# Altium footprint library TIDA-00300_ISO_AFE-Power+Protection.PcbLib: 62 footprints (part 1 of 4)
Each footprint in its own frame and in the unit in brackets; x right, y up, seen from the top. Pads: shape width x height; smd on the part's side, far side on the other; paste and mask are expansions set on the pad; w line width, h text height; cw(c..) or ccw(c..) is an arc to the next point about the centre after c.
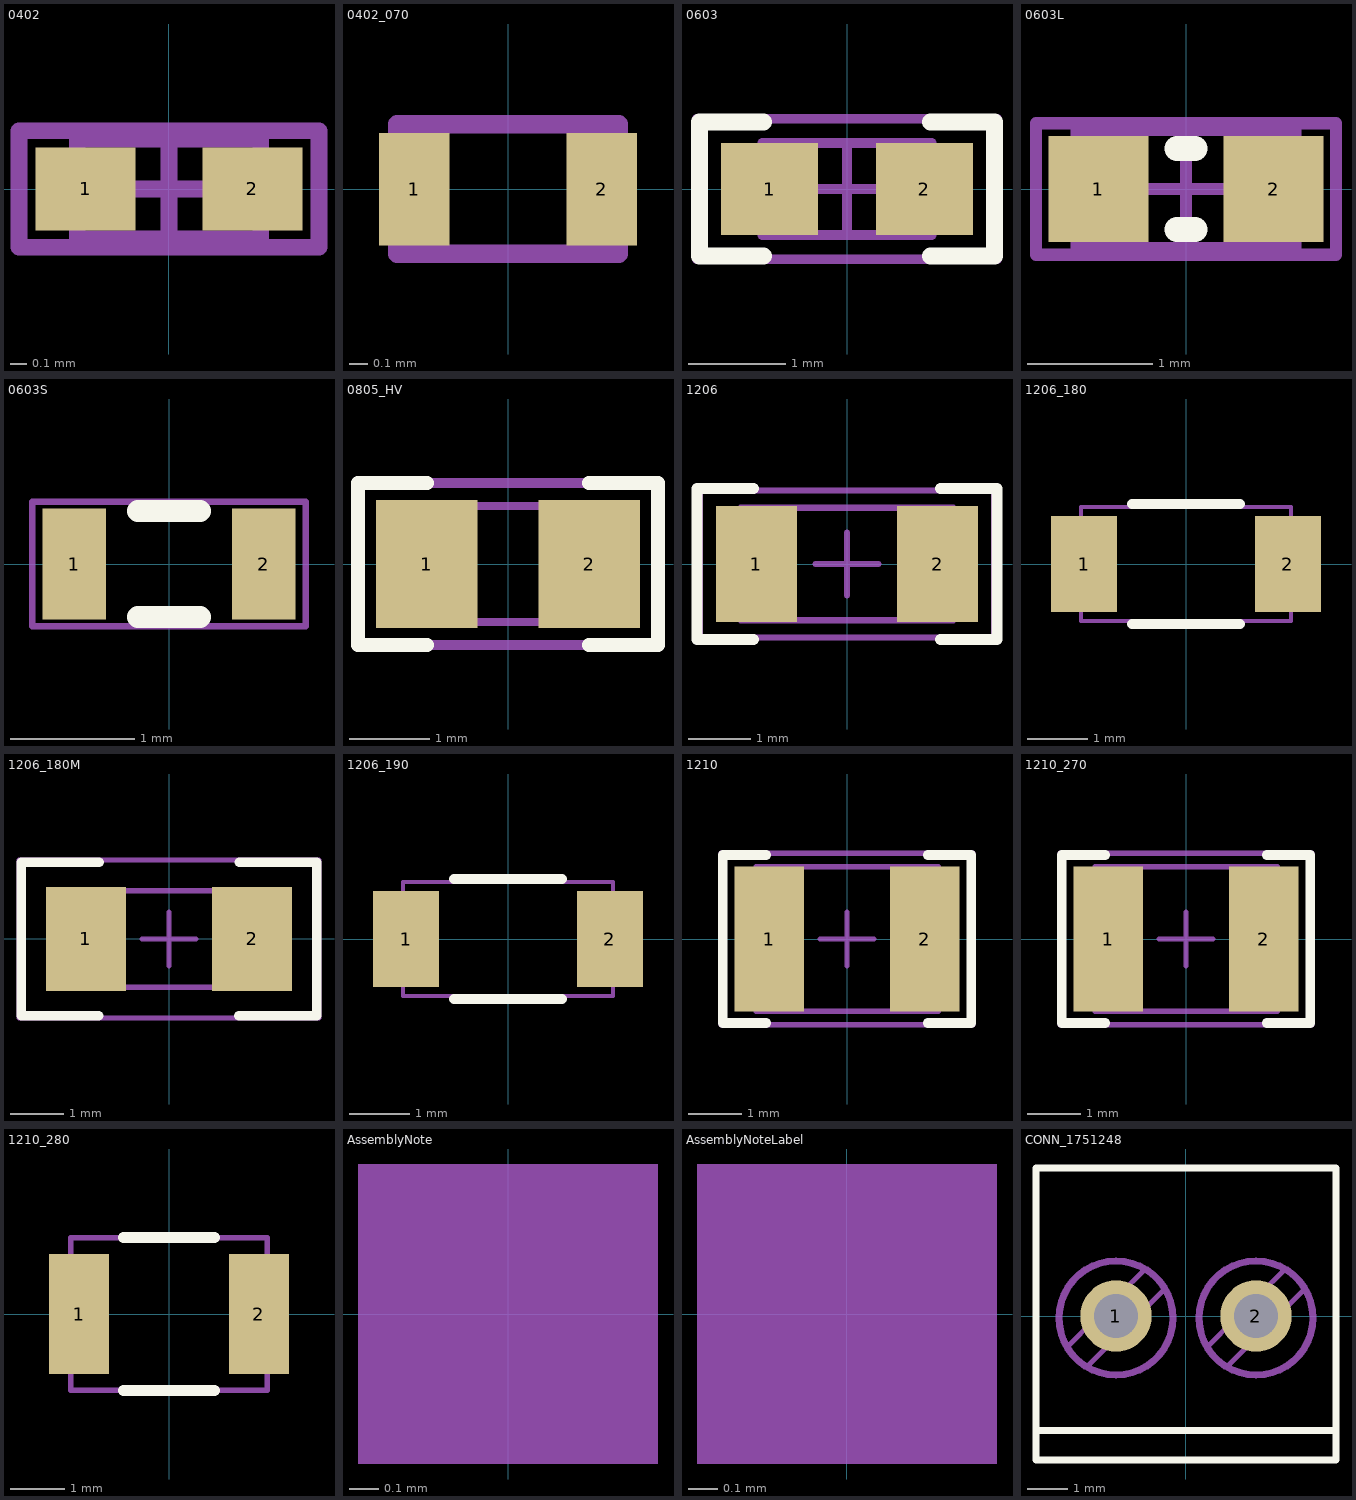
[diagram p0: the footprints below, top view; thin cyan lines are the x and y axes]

## 0402 [mm] "Chip Capacitor, Body 1.0x0.5mm, IPC High Density"
height 1.3
pads (2):
  rect 0.6x0.5 smd: 1(-0.5,0) 2(0.5,0)
Mechanical 5:
  lines w0.1: -0.55,-0.3 -0.55,0.3 0.55,0.3 0.55,-0.3 -0.55,-0.3
  text ".Designator" at 0,0 h0.51
Mechanical 13:
  lines w0.1: -0.55,-0.3 0.55,-0.3 0.55,0.3 -0.55,0.3 -0.55,-0.3
Mechanical 15:
  lines w0.1: -0.3,0 0.3,0 ; 0,-0.3 0,0.3 ; -0.9,-0.35 0.9,-0.35 0.9,0.35 -0.9,0.35 -0.9,-0.35
3D body: height 1.3, standoff 0, extent -0.55,-0.3 0.55,0.3

## 0402_070 [mil] "SMD, 2-Leads, Body 1.2x0.7mm, Height 0.7mm"
height 27.56
pads (2):
  rect 15x24 smd: 1(-20,0) 2(20,0)
Mechanical 5:
  lines w3.94: -23.62,-13.78 -23.62,13.78 23.62,13.78 23.62,-13.78 -23.62,-13.78
  text ".Designator" at 27.43,44.99 h20
3D body: height 27.56, standoff 0, extent 13.78,-13.78 23.62,13.78
3D body: height 27.56, standoff 0, extent -23.62,-13.78 -13.78,13.78
3D body: height 27.56, standoff 0, extent -13.78,-13.78 13.78,13.78

## 0603 [mm] "0603 from SM-752 data"
height 1
pads (2):
  rect 1x0.95 smd: 1(-0.8,0) 2(0.8,0)
Top Overlay:
  lines w0.178: -0.864,-0.691 -1.524,-0.691 -1.524,0.693 -0.864,0.693 ; 0.864,-0.691 1.524,-0.691 1.524,0.693 0.864,0.693
Mechanical 5:
  lines w0.1: -1.55,-0.725 1.55,-0.725 1.55,0.725 -1.55,0.725 -1.55,-0.725
  text ".Designator" at 0.813,0.178 h0.51
Mechanical 13:
  lines w0.1: -0.55,-0.475 -0.55,0.475 ; 0.55,-0.475 0.55,0.475 ; -0.875,-0.475 -0.875,0.475 0.875,0.475 0.875,-0.475 -0.875,-0.475
Mechanical 15:
  lines w0.1: -0.475,0 0.475,0 ; 0,-0.475 0,0.475 ; -1.55,-0.725 -1.55,0.725 1.55,0.725 1.55,-0.725 -1.55,-0.725
3D body: height 1, standoff 0, extent 0.551,-0.474 0.874,0.474
3D body: height 1, standoff 0, extent -0.549,-0.474 0.549,0.474
3D body: height 1, standoff 0, extent -0.874,-0.474 -0.551,0.474

## 0603L [mm] "0603 from SM-752 data"
height 1
pads (2):
  rect 0.8x0.85 smd: 1(-0.7,0) 2(0.7,0)
Top Overlay:
  lines w0.2: -0.071,-0.325 0.071,-0.325 ; -0.071,0.325 0.071,0.325
Mechanical 5:
  lines w0.1: -1.2,-0.525 -1.2,0.525 1.2,0.525 1.2,-0.525 -1.2,-0.525
  text ".Designator" at 0.301,0.222 h0.51
Mechanical 13:
  lines w0.1: -0.55,-0.475 -0.55,0.475 ; 0.55,-0.475 0.55,0.475 ; -0.875,-0.475 -0.875,0.475 0.875,0.475 0.875,-0.475 -0.875,-0.475
Mechanical 15:
  lines w0.1: -0.475,0 0.475,0 ; 0,-0.475 0,0.475 ; -1.2,-0.525 -1.2,0.525 1.2,0.525 1.2,-0.525 -1.2,-0.525
3D body: height 1, standoff 0, extent -0.874,-0.474 -0.551,0.474
3D body: height 1, standoff 0, extent -0.549,-0.474 0.549,0.474
3D body: height 1, standoff 0, extent 0.551,-0.474 0.874,0.474

## 0603S [mil]
height 39.37
pads (2):
  rect 20x35 smd: 1(-30,0) 2(30,0)
Top Overlay:
  lines w7: -9.84,-16.73 9.84,-16.73 ; -9.84,16.73 9.84,16.73
Mechanical 5:
  lines w1.97: -43.31,-19.68 -43.31,19.68 43.31,19.68 43.31,-19.68 -43.31,-19.68
  text ".Designator" at 32,10.72 h20
3D body: height 39.37, standoff 0, extent 21.67,-18.68 34.43,18.68
3D body: height 39.37, standoff 0, extent -21.63,-18.68 21.63,18.68
3D body: height 39.37, standoff 0, extent -34.43,-18.68 -21.67,18.68

## 0805_HV [mil] "0805 with 30mil clearance between pads"
height 57.09
pads (2):
  rect 50x63 smd: 1(-40,0) 2(40,0)
Top Overlay:
  lines w7: -40,-40 -74,-40 -74,0 -74,40 -40,40 ; 40,-40 74,-40 74,0 74,40 40,40
Mechanical 5:
  lines w5: -74,-40 74,-40 74,40 -74,40 -74,-40
  text ".Designator" at 21.89,3.88 h20
Mechanical 13:
  lines w3.94: -25.59,-28.54 -25.59,28.54 ; 25.59,-28.54 25.59,28.54 ; -43.31,-28.54 43.31,-28.54 43.31,28.54 -43.31,28.54 -43.31,-28.54
3D body: height 57.09, standoff 0, extent 25.61,-28.52 43.29,28.52
3D body: height 57.09, standoff 0, extent -43.29,-28.52 -25.61,28.52
3D body: height 57.09, standoff 0, extent -25.57,-28.52 25.57,28.52

## 1206 [mm] "1206 from SM-752 data"
height 1.35
pads (2):
  rect 1.3x1.85 smd: 1(-1.45,0) 2(1.45,0)
Top Overlay:
  lines w0.178: -1.5,-1.21 -2.4,-1.21 -2.4,1.21 -1.5,1.21 ; 1.5,-1.21 2.4,-1.21 2.4,1.21 1.5,1.21
Mechanical 5:
  lines w0.1: -1.7,-0.9 1.7,-0.9 1.7,0.9 -1.7,0.9 -1.7,-0.9
  text ".Designator" at 0.838,0.229 h0.51
Mechanical 13:
  lines w0.1: -1.2,-0.9 -1.2,0.9 ; 1.2,-0.9 1.2,0.9 ; -1.7,-0.9 1.7,-0.9 1.7,0.9 -1.7,0.9 -1.7,-0.9
Mechanical 15:
  lines w0.1: -0.5,0 0.5,0 ; 0,-0.5 0,0.5 ; -2.35,-1.175 2.35,-1.175 2.35,1.175 -2.35,1.175 -2.35,-1.175
3D body: height 1.35, standoff 0, extent -1.699,-0.899 -1.201,0.899
3D body: height 1.35, standoff 0, extent -1.199,-0.899 1.199,0.899
3D body: height 1.35, standoff 0, extent 1.201,-0.899 1.699,0.899

## 1206_180 [mm] "1206_180"
height 1.8
pads (2):
  rect 1.1x1.6 smd: 1(-1.7,0) 2(1.7,0)
Top Overlay:
  lines w0.17: -0.9,-1 0.9,-1 ; -0.9,1 0.9,1
Mechanical 5:
  lines w0.07: -1.75,-0.95 -1.75,0.95 1.75,0.95 1.75,-0.95 -1.75,-0.95
  text ".Designator" at 0.917,0.277 h0.51
3D body: height 1.8, standoff 0, extent 1.301,-0.949 1.749,0.949
3D body: height 1.8, standoff 0, extent -1.299,-0.949 1.299,0.949
3D body: height 1.8, standoff 0, extent -1.749,-0.949 -1.301,0.949

## 1206_180M [mm] "1206_180"
height 1.8
pads (2):
  rect 1.5x1.95 smd: 1(-1.55,0) 2(1.55,0)
Top Overlay:
  lines w0.178: -2.758,-1.43 -2.753,-1.435 ; -1.313,-1.435 -2.758,-1.435 -2.758,1.435 -1.303,1.435 ; 1.306,-1.435 2.761,-1.435 2.761,1.435 1.316,1.435 ; 2.756,1.435 2.761,1.43
Mechanical 5:
  lines w0.1: -1.7,-0.9 1.7,-0.9 1.7,0.9 -1.7,0.9 -1.7,-0.9
  text ".Designator" at 0.961,0.271 h0.51
Mechanical 15:
  lines w0.1: -0.5,0 0.5,0 ; 0,-0.5 0,0.5 ; -2.8,-1.475 -2.8,1.475 2.8,1.475 2.8,-1.475 -2.8,-1.475
3D body: height 1.8, standoff 0, extent 1.301,-0.949 1.75,0.95
3D body: height 1.8, standoff 0, extent -1.299,-0.949 1.3,0.95
3D body: height 1.8, standoff 0, extent -1.749,-0.949 -1.3,0.95

## 1206_190 [mm] "1206_190"
height 1.9
pads (2):
  rect 1.1x1.6 smd: 1(-1.7,0) 2(1.7,0)
Top Overlay:
  lines w0.17: -0.9,-1 0.9,-1 ; -0.9,1 0.9,1
Mechanical 5:
  lines w0.07: -1.75,-0.95 -1.75,0.95 1.75,0.95 1.75,-0.95 -1.75,-0.95
  text ".Designator" at 0.504,0.374 h0.51
3D body: height 1.9, standoff 0, extent -1.749,-0.949 -1.301,0.949
3D body: height 1.9, standoff 0, extent -1.299,-0.949 1.299,0.949
3D body: height 1.9, standoff 0, extent 1.301,-0.949 1.749,0.949

## 1210 [mm] "1210 from SM-752 data"
height 1.35
pads (2):
  rect 1.3x2.7 smd: 1(-1.45,0) 2(1.45,0)
Top Overlay:
  lines w0.178: -1.511,-1.568 -2.316,-1.568 -2.316,1.568 -1.511,1.568 ; 1.511,-1.568 2.316,-1.568 2.316,1.568 1.511,1.568
Mechanical 5:
  lines w0.1: -1.7,-1.35 -1.7,1.35 1.7,1.35 1.7,-1.35 -1.7,-1.35
  text ".Designator" at -0.889,-0.381 h0.51
Mechanical 13:
  lines w0.1: -1.2,-1.35 -1.2,1.35 ; 1.2,-1.35 1.2,1.35 ; -1.7,-1.35 1.7,-1.35 1.7,1.35 -1.7,1.35 -1.7,-1.35
Mechanical 15:
  lines w0.1: -0.5,0 0.5,0 ; 0,-0.5 0,0.5 ; -2.35,-1.6 2.35,-1.6 2.35,1.6 -2.35,1.6 -2.35,-1.6
3D body: height 1.35, standoff 0, extent 1.201,-1.349 1.699,1.349
3D body: height 1.35, standoff 0, extent -1.199,-1.349 1.199,1.349
3D body: height 1.35, standoff 0, extent -1.699,-1.349 -1.201,1.349

## 1210_270 [mm] "1210"
height 2.7
pads (2):
  rect 1.3x2.7 smd: 1(-1.45,0) 2(1.45,0)
Top Overlay:
  lines w0.178: -1.511,-1.568 -2.316,-1.568 -2.316,1.568 -1.511,1.568 ; 1.511,-1.568 2.316,-1.568 2.316,1.568 1.511,1.568
Mechanical 5:
  lines w0.1: -1.7,-1.35 -1.7,1.35 1.7,1.35 1.7,-1.35 -1.7,-1.35
  text ".Designator" at -0.308,-0.277 h0.51
Mechanical 13:
  lines w0.1: -1.2,-1.35 -1.2,1.35 ; 1.2,-1.35 1.2,1.35 ; -1.7,-1.35 1.7,-1.35 1.7,1.35 -1.7,1.35 -1.7,-1.35
Mechanical 15:
  lines w0.1: -0.5,0 0.5,0 ; 0,-0.5 0,0.5 ; -2.35,-1.6 2.35,-1.6 2.35,1.6 -2.35,1.6 -2.35,-1.6
3D body: height 2.7, standoff 0, extent 1.201,-1.349 1.699,1.349
3D body: height 2.7, standoff 0, extent -1.199,-1.349 1.199,1.349
3D body: height 2.7, standoff 0, extent -1.699,-1.349 -1.201,1.349

## 1210_280 [mm] "SMD, 2-Leads, Body 3.6x2.8mm, Height 2.8mm"
height 2.8
pads (2):
  rect 1.1x2.2 smd: 1(-1.65,0) 2(1.65,0)
Top Overlay:
  lines w0.2: -0.835,-1.4 0.835,-1.4 ; -0.835,1.4 0.835,1.4
Mechanical 5:
  lines w0.1: -1.8,-1.4 -1.8,1.4 1.8,1.4 1.8,-1.4 -1.8,-1.4
  text ".Designator" at -0.841,-0.2 h0.51
3D body: height 2.8, standoff 0, extent -1.8,-1.4 -1.6,1.4
3D body: height 2.8, standoff 0, extent -1.6,-1.4 1.6,1.4
3D body: height 2.8, standoff 0, extent 1.6,-1.4 1.8,1.4

## AssemblyNote [mm] "Assembly Note"
Mechanical 5:
  rectangle: -0.508,-0.508 0.508,0.508
  text ".Comment" at 1.143,-0.508 h0.51
  text ".Designator" at -4.191,-0.508 h0.51

## AssemblyNoteLabel [mm] "Assembly Note for PCB Labels"
Mechanical 5:
  rectangle: -0.508,-0.508 0.508,0.508
  text "Install label in silkscreened box after final wash.  Text shall be 8 pt font.  Text shall be per the Label Table in the PDF schematic." at 1.143,-0.508 h0.51
  text ".Designator" at -4.191,-0.508 h0.51

## CONN_1751248 [mm] "Phoenix Contact"
height 8.5
pads (2):
  round 1.778 hole 1.1: 1(-1.75,0) 2(1.75,0)
Top Overlay:
  lines w0.178: -3.75,-2.861 3.75,-2.861 ; -3.75,-2.861 -3.75,-3.3 -3.75,-3.6 3.75,-3.6 3.75,-3.3 3.75,-2.861 ; -3.75,-2.861 -3.75,-2.049 -3.75,-1.566 -3.75,1.487 -3.75,1.962 -3.75,3.7 3.75,3.7 3.75,1.962 3.75,1.487 3.75,-1.566 3.75,-2.049 3.75,-2.861
Mechanical 5:
  lines w0.127: -3.75,-2.861 -3.75,-2.049 -3.75,-1.566 -3.75,1.487 -3.75,1.962 -3.75,3.7 3.75,3.7 3.75,1.962 3.75,1.487 3.75,-1.566 3.75,-2.049 3.75,-2.861 ; -3.75,-2.861 -3.75,-3.3 -3.75,-3.6 3.75,-3.6 3.75,-3.3 3.75,-2.861 ; -3.75,-2.861 3.75,-2.861 ; -2.956,-0.761 ccw(c-1.75,-0.05) -2.461,-1.256 ; -2.956,-0.761 cw(c-1.75,-0.05) -1.75,1.35 cw(c-1.75,-0.05) -1.039,1.156 ; -2.956,-0.761 -2.291,-0.096 -1.75,0.445 -1.653,0.542 -1.039,1.156 ; -2.461,-1.256 ccw(c-1.75,-0.05) -1.75,-1.45 ccw(c-1.75,-0.05) -0.544,0.661 ; -2.461,-1.256 -1.755,-0.55 -1.75,-0.545 -1.2,0.005 -0.544,0.661 ; -1.039,1.156 cw(c-1.75,-0.05) -0.544,0.661 ; 0.544,-0.761 cw(c1.75,-0.05) 1.75,1.35 cw(c1.75,-0.05) 2.461,1.156 ; 0.544,-0.761 ccw(c1.75,-0.05) 1.039,-1.256 ; 0.544,-0.761 1.209,-0.096 1.75,0.445 1.847,0.542 2.461,1.156 ; 1.039,-1.256 ccw(c1.75,-0.05) 1.75,-1.45 ccw(c1.75,-0.05) 2.956,0.661 ; 1.039,-1.256 1.745,-0.55 1.75,-0.545 2.3,0.005 2.956,0.661 ; 2.461,1.156 cw(c1.75,-0.05) 2.956,0.661 ; -1.75,-1.5 cw(c-1.75,-0.05) -1.75,1.4 cw(c-1.75,-0.05) -1.75,-1.5 ; 1.75,-1.5 cw(c1.75,-0.05) 1.75,1.4 cw(c1.75,-0.05) 1.75,-1.5
  text ".Designator" at -0.579,2.841 h0.51
3D body "Phoenix_1751248.stp": height 8.52, standoff -3.48, extent -3.75,-3.6 3.75,3.7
